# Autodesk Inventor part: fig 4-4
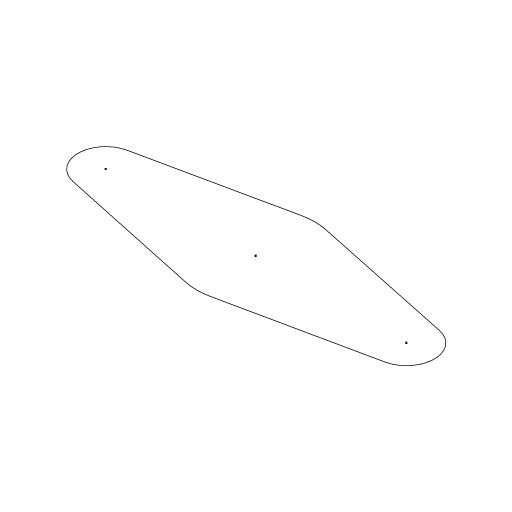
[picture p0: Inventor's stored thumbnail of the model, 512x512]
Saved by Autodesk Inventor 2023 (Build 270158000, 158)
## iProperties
Created: 2005-02
Part Number: fig 4-4
Document SubType Name: Modeling
Designer: CADCIM
Manufacturer: Standard
Standards Organization: Custom
Density: 1 g/cm^3
Material: Generic
Appearance: Default
Author: CADCIM
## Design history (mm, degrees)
sketch "Sketch1"
  geometry: L1 (-33.874, 5.844)-(-2.722, 12.469); L2 (2.595, 12.472)-(33.871, 5.852); L3 (-33.884, -5.902)-(-2.745, -12.585); L4 (2.595, -12.592)-(33.871, -5.972); A1 r 6.006 centre (-32.624, -0.03) between (-33.874, 5.844) and (-33.884, -5.902); A2 r 6.043 centre (32.619, -0.06) between (33.871, -5.972) and (33.871, 5.852); A3 r 12.81 centre (-0.057, -0.06) between (-2.745, -12.585) and (2.595, -12.592); A4 r 12.81 centre (-0.057, -0.06) between (2.595, 12.472) and (-2.722, 12.469)
  constraints: 8 end point, 8 point on circle, 8 tangent, 4 centre point, 1 other
